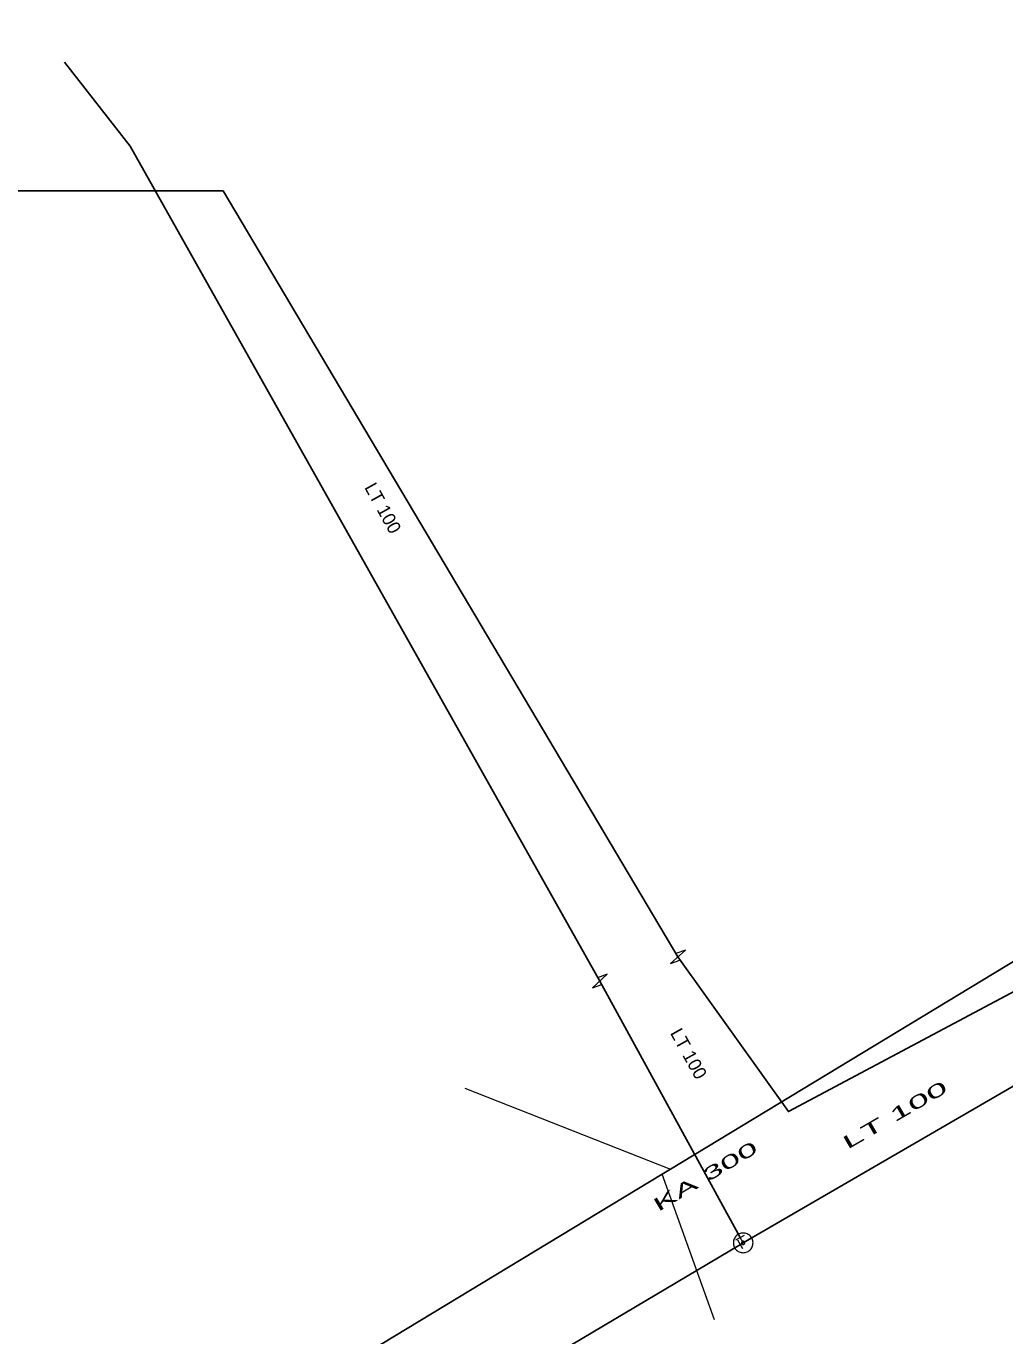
# Model space of a CAD drawing. Extents: x -687468 to -685917, y -974192 to -973456.
# Drawn here: x -686251.8 to -686202, y -973594.5 to -973527.9 of the extents above; entities that cross this region are included whole.
import ezdxf
from ezdxf.enums import TextEntityAlignment as Align

# ---------------------------------------------------------------- set-up
doc = ezdxf.new("R2010")
doc.units = 0
doc.header["$LTSCALE"] = 0.27
for name, color, linetype, lineweight in [('1', 7, 'Continuous', 13), ('11', 7, 'Continuous', 13), ('14', 7, 'Continuous', 25), ('17', 7, 'Continuous', 25), ('34', 7, 'Continuous', 13), ('47', 7, 'Continuous', 13)]:
    doc.layers.add(name, color=color, linetype=linetype, lineweight=lineweight)

msp = doc.modelspace()

# ---------------------------------------------------------------- linework, layer by layer
at = {"layer": '11'}
for p, q in [((-686229.521, -973581.932), (-686219.052, -973586.057)), ((-686216.8, -973593.73), (-686219.48, -973586.316))]:
    msp.add_line(p, q, dxfattribs=at)
at = {"layer": '14', "lineweight": 13}
for q in [(-686215.499, -973589.529), (-686215.489, -973589.889)]:
    msp.add_line((-686215.348, -973589.807), q, dxfattribs=at)
at = {"layer": '14'}
msp.add_lwpolyline([(-686235.469, -973596), (-686234.388, -973595.344), (-686219.48, -973586.316), (-686219.052, -973586.057), (-686200.73, -973574.96), (-686199.012, -973577.618)], dxfattribs=at)
at = {"layer": '17'}
for p, q in [((-686215.499, -973589.529), (-686222.649, -973576.479)), ((-686198.489, -973580.019), (-686215.348, -973589.807))]:
    msp.add_line(p, q, dxfattribs=at)
for points in [[(-686218.669, -973575.249), (-686241.82, -973536.249), (-686259.82, -973536.249), (-686297.706, -973538.254), (-686327.845, -973538.199), (-686349.52, -973536.783), (-686380.82, -973530.249), (-686437.82, -973510.249), (-686501.82, -973481.249), (-686564.449, -973459.96), (-686572.82, -973456.199)], [(-686222.649, -973576.479), (-686246.554, -973533.985), (-686249.897, -973529.71)], [(-686148.68, -973547.12), (-686199.359, -973575.84), (-686213.05, -973583.12), (-686218.669, -973575.249)], [(-686215.348, -973589.807), (-686215.489, -973589.889), (-686241.84, -973605.539), (-686260.53, -973614.85), (-686290.159, -973621.799)]]:
    msp.add_lwpolyline(points, dxfattribs=at)
at = {"layer": '34'}
for p, q in [((-686215.716, -973589.647), (-686215.281, -973589.41)), ((-686215.364, -973590.103), (-686215.613, -973589.674))]:
    msp.add_line(p, q, dxfattribs=at)
at = {"layer": '47'}
for p, q in [((-686218.29, -973574.908), (-686218.772, -973575.076)), ((-686222.279, -973576.128), (-686222.756, -973576.309))]:
    msp.add_line(p, q, dxfattribs=at)
for points in [[(-686218.29, -973574.908), (-686219.047, -973575.589), (-686218.565, -973575.421)], [(-686222.279, -973576.128), (-686223.018, -973576.829), (-686222.541, -973576.648)]]:
    msp.add_lwpolyline(points, dxfattribs=at)
for points in [[(-686214.848, -973589.808), (-686214.851, -973589.755), (-686214.859, -973589.703), (-686214.873, -973589.654), (-686214.891, -973589.605), (-686214.915, -973589.558), (-686214.944, -973589.514), (-686214.977, -973589.473), (-686215.014, -973589.436), (-686215.054, -973589.404), (-686215.098, -973589.375), (-686215.145, -973589.35), (-686215.194, -973589.333), (-686215.244, -973589.319), (-686215.296, -973589.311), (-686215.348, -973589.308), (-686215.4, -973589.311), (-686215.452, -973589.319), (-686215.503, -973589.333), (-686215.551, -973589.35), (-686215.598, -973589.375), (-686215.642, -973589.404), (-686215.683, -973589.436), (-686215.72, -973589.473), (-686215.753, -973589.514), (-686215.781, -973589.558), (-686215.805, -973589.605), (-686215.824, -973589.654), (-686215.837, -973589.703), (-686215.845, -973589.755), (-686215.848, -973589.808), (-686215.845, -973589.86), (-686215.837, -973589.912), (-686215.824, -973589.963), (-686215.805, -973590.011), (-686215.781, -973590.058), (-686215.753, -973590.102), (-686215.72, -973590.142), (-686215.683, -973590.179), (-686215.642, -973590.213), (-686215.598, -973590.24), (-686215.551, -973590.265), (-686215.503, -973590.284), (-686215.452, -973590.296), (-686215.4, -973590.304), (-686215.348, -973590.308), (-686215.296, -973590.304), (-686215.244, -973590.296), (-686215.194, -973590.284), (-686215.145, -973590.265), (-686215.098, -973590.24), (-686215.054, -973590.213), (-686215.014, -973590.179), (-686214.977, -973590.142), (-686214.944, -973590.102), (-686214.915, -973590.058), (-686214.891, -973590.011), (-686214.873, -973589.963), (-686214.859, -973589.912), (-686214.851, -973589.86)], [(-686215.266, -973589.808), (-686215.266, -973589.799), (-686215.268, -973589.791), (-686215.27, -973589.782), (-686215.273, -973589.774), (-686215.277, -973589.767), (-686215.282, -973589.76), (-686215.287, -973589.752), (-686215.293, -973589.747), (-686215.3, -973589.742), (-686215.307, -973589.737), (-686215.315, -973589.733), (-686215.323, -973589.73), (-686215.331, -973589.728), (-686215.339, -973589.725), (-686215.348, -973589.725), (-686215.357, -973589.725), (-686215.365, -973589.728), (-686215.373, -973589.73), (-686215.381, -973589.733), (-686215.389, -973589.737), (-686215.396, -973589.742), (-686215.403, -973589.747), (-686215.409, -973589.752), (-686215.415, -973589.76), (-686215.419, -973589.767), (-686215.423, -973589.774), (-686215.426, -973589.782), (-686215.428, -973589.791), (-686215.43, -973589.799), (-686215.43, -973589.808), (-686215.43, -973589.816), (-686215.428, -973589.825), (-686215.426, -973589.833), (-686215.423, -973589.841), (-686215.419, -973589.848), (-686215.415, -973589.855), (-686215.409, -973589.863), (-686215.403, -973589.869), (-686215.396, -973589.875), (-686215.389, -973589.879), (-686215.381, -973589.882), (-686215.373, -973589.886), (-686215.365, -973589.887), (-686215.357, -973589.89), (-686215.348, -973589.89), (-686215.339, -973589.89), (-686215.331, -973589.887), (-686215.323, -973589.886), (-686215.315, -973589.882), (-686215.307, -973589.879), (-686215.3, -973589.875), (-686215.293, -973589.869), (-686215.287, -973589.863), (-686215.282, -973589.855), (-686215.277, -973589.848), (-686215.273, -973589.841), (-686215.27, -973589.833), (-686215.268, -973589.825), (-686215.266, -973589.816)]]:
    msp.add_lwpolyline(points, close=True, dxfattribs=at)

# ---------------------------------------------------------------- texts
at = {"layer": '1'}
for p in [(-686233.976, -973552.566), (-686218.414, -973580.336)]:
    msp.add_text('LT 100', height=0.6667, rotation=299, dxfattribs=at).set_placement(p, align=Align.CENTER)
for s, rotation, width, p in [('LT 100', 30, 2.15, (-686207.46, -973583.579)), ('KA 300', 31, 2.05, (-686217.105, -973586.696))]:
    msp.add_text(s, height=0.6667, rotation=rotation, dxfattribs=dict(at, width=width)).set_placement(p, align=Align.CENTER)

doc.saveas('drawing.dxf')
